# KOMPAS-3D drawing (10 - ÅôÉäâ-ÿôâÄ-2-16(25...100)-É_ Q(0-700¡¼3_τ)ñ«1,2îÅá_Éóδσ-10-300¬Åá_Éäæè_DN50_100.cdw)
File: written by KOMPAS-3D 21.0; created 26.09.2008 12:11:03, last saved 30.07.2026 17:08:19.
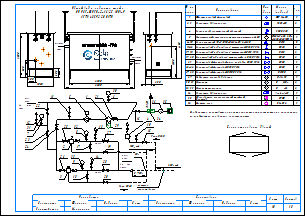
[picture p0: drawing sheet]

Sheets 1-2: A3, landscape

Document properties: Наименование: Макро:21; Автор: RaskoAdmin; Форматы листов документа: 2xA3; Полное имя файла: \\ur38nt01\Departments\КТО\КБ ПУРДГ\Заявки\Прайс-лист на типовые шкафы ГРПШ\ПУРДГ_стандарт_30_04_2026\ПУРДГ с РДСК\ПУРДГ-ШУГО-2-16(25...100)-Р_ Q(0-700нм3_ч)до1,2МПа_Рвых-10-300кПа_РДСК_DN50_100.cdw

Title block, sheet 1: Наименование: Пункт учета газа / ПУГ-Ш-400-Р / ЛГТИ.485922.001ТУ; designation: ЛГТИ.03.4411141; sheet number: 1; Количество листов документа: 2; organisation: ООО "ЭЛЬСТЕР Газэлектроника"; Форматы листов документа: A3; stored path: C:\Рабочие документы\Компас\ПУГ\Схема.cdw; Разработал: Устинов; Проверил: Кошкин; Утвердил: Кошкин
Title block, sheet 2: sheet number: 2; stored path: D:\Рабочие документы\Заявки\ПУРДГ\ПУРДГ-ШУЭО-2-100-Р 4411220.cdw; designation, second copy: ЛГТИ.03.4411141-

Views: Вид 1, Вид 2
Referenced files: wcvoit.frw
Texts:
  Normal
  Общий вид и габариты шкафа
  ПУРДГ-ШУГО-2-16(25...100)-Р
  DN100
  Выход газа
  DN50
  Вход газа
  logo-rasko-ge.png
  DN 1
  местное
  сопротивление
  Римп DN20
  Выход
  газа
  Р=     кПа
  Вход
  Р=       МПа
  PDI
  № на
  схеме
  Усл.
  обозн.
  Марка
  (модель)
  Кол.
  Фильтр газовый фланцевый
  ФГ 16-50
  Регулятор давления газа
  РДСК-50
  Клапан предохранительный сбросной
  КПС DN20
  Измерительный комплекс с ротационным счетчиком Ду50
  СГ-ЭК-Р-(0,2...2,0)-
  Кран кнопочный VE-РАСКО-НЗ-1,6-G1/2-М20
  DN15
  Кран шаровой "под приварку" штуцерный DN20 PN16
  DN20
  Кран шаровой "под приварку" штуцерный DN15 PN16
  Кран шаровой "под приварку" штуцерный п/п DN20 PN16
  Кран шаровой фланцевый с мех. приводом DN50 PN16
  Кран шаровой фланцевый DN50 PN16
  Кран шаровой фланцевый DN100 PN16
  Индикатор перепада давления
  Манометр
  Манометр-напоромер
  Обогреватель газогорелочный шкафной
  (Эльтон")
  Счетчик газа
  Delta 15
  0...     МПа
  0...     кПа
  Venio-A-15
  ОГШН
  BK-G1,6
  Схема открывания дверей
  Предприятие изготовитель может заменять комплектующие на аналогичные,
  не ухудшающие заявленных характеристик.
  Должность
  Конструктор
  Фамилия
  Подпись
  Дата
  Согласовано
  Максимкин
  Лист
  Листов
  POLYLINE_STYLE_0.18_RGB_0_0_0
  POLYLINE_STYLE_0.50_RGB_0_0_0
  POLYLINE_STYLE_0.34_RGB_0_0_0
  PHANTOM_RGB_0_0_0_SC_1_THICK_0.18
  K5LT_THIN_RGB_0_0_0_THICK_0.18
  K5LT32769_RGB_0_0_0_THICK_0.18
  K5LT12_RGB_0_0_0_SC_1_THICK_0.18
  K5LT_DASHED_RGB_0_0_0_SC_1_THICK_0.18
  ACISOTGL_RGB_0_0_0_SC_0.8_THICK_0.25
  CONTINUOUS_RGB_0_127_31_THICK_0.3
  CONTINUOUS_RGB_0_0_255_THICK_0.35
  CONTINUOUS_RGB_255_0_0_THICK_0.35
  POLYLINE_STYLE_0.25_RGB_0_0_0
  CONTINUOUS_RGB_0_0_0_THICK_0.5
  POLYLINE_STYLE_0.35_RGB_0_0_255
  CONTINUOUS_RGB_0_0_0_THICK_0.4
  CONTINUOUS_RGB_0_0_0_THICK_0.35
  НЕВИДИМАЯ_RGB_0_0_0_SC_0.3_THICK_0.25
  СONTINUOUS_RGB_0_0_0_THICK_0.25
  ОСЕВАЯ2_RGB_248_153_30_SC_0.3_THICK_0.25
  Без оформления
Dimensions and other numbers on the sheet: 1; 1500; 250; 300; 1050; 550; 305; 2300; 4130; 2000; 2600; 5,,,7DN 1; 7; 31; 12; 22; 23; 24; 11; 5; 21; 6; 30; 25; 32; 8; 2; 17; 13; 27; 19; 4; 10; 15; 26; 33; 9; 3; 18; 14; 28; 20; 29; 2, 3; 6-10; 11-16; 17, 18; 19, 20; 22-26; 27, 28; 30, 31; 32, 33; 34; 35; 36; 16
